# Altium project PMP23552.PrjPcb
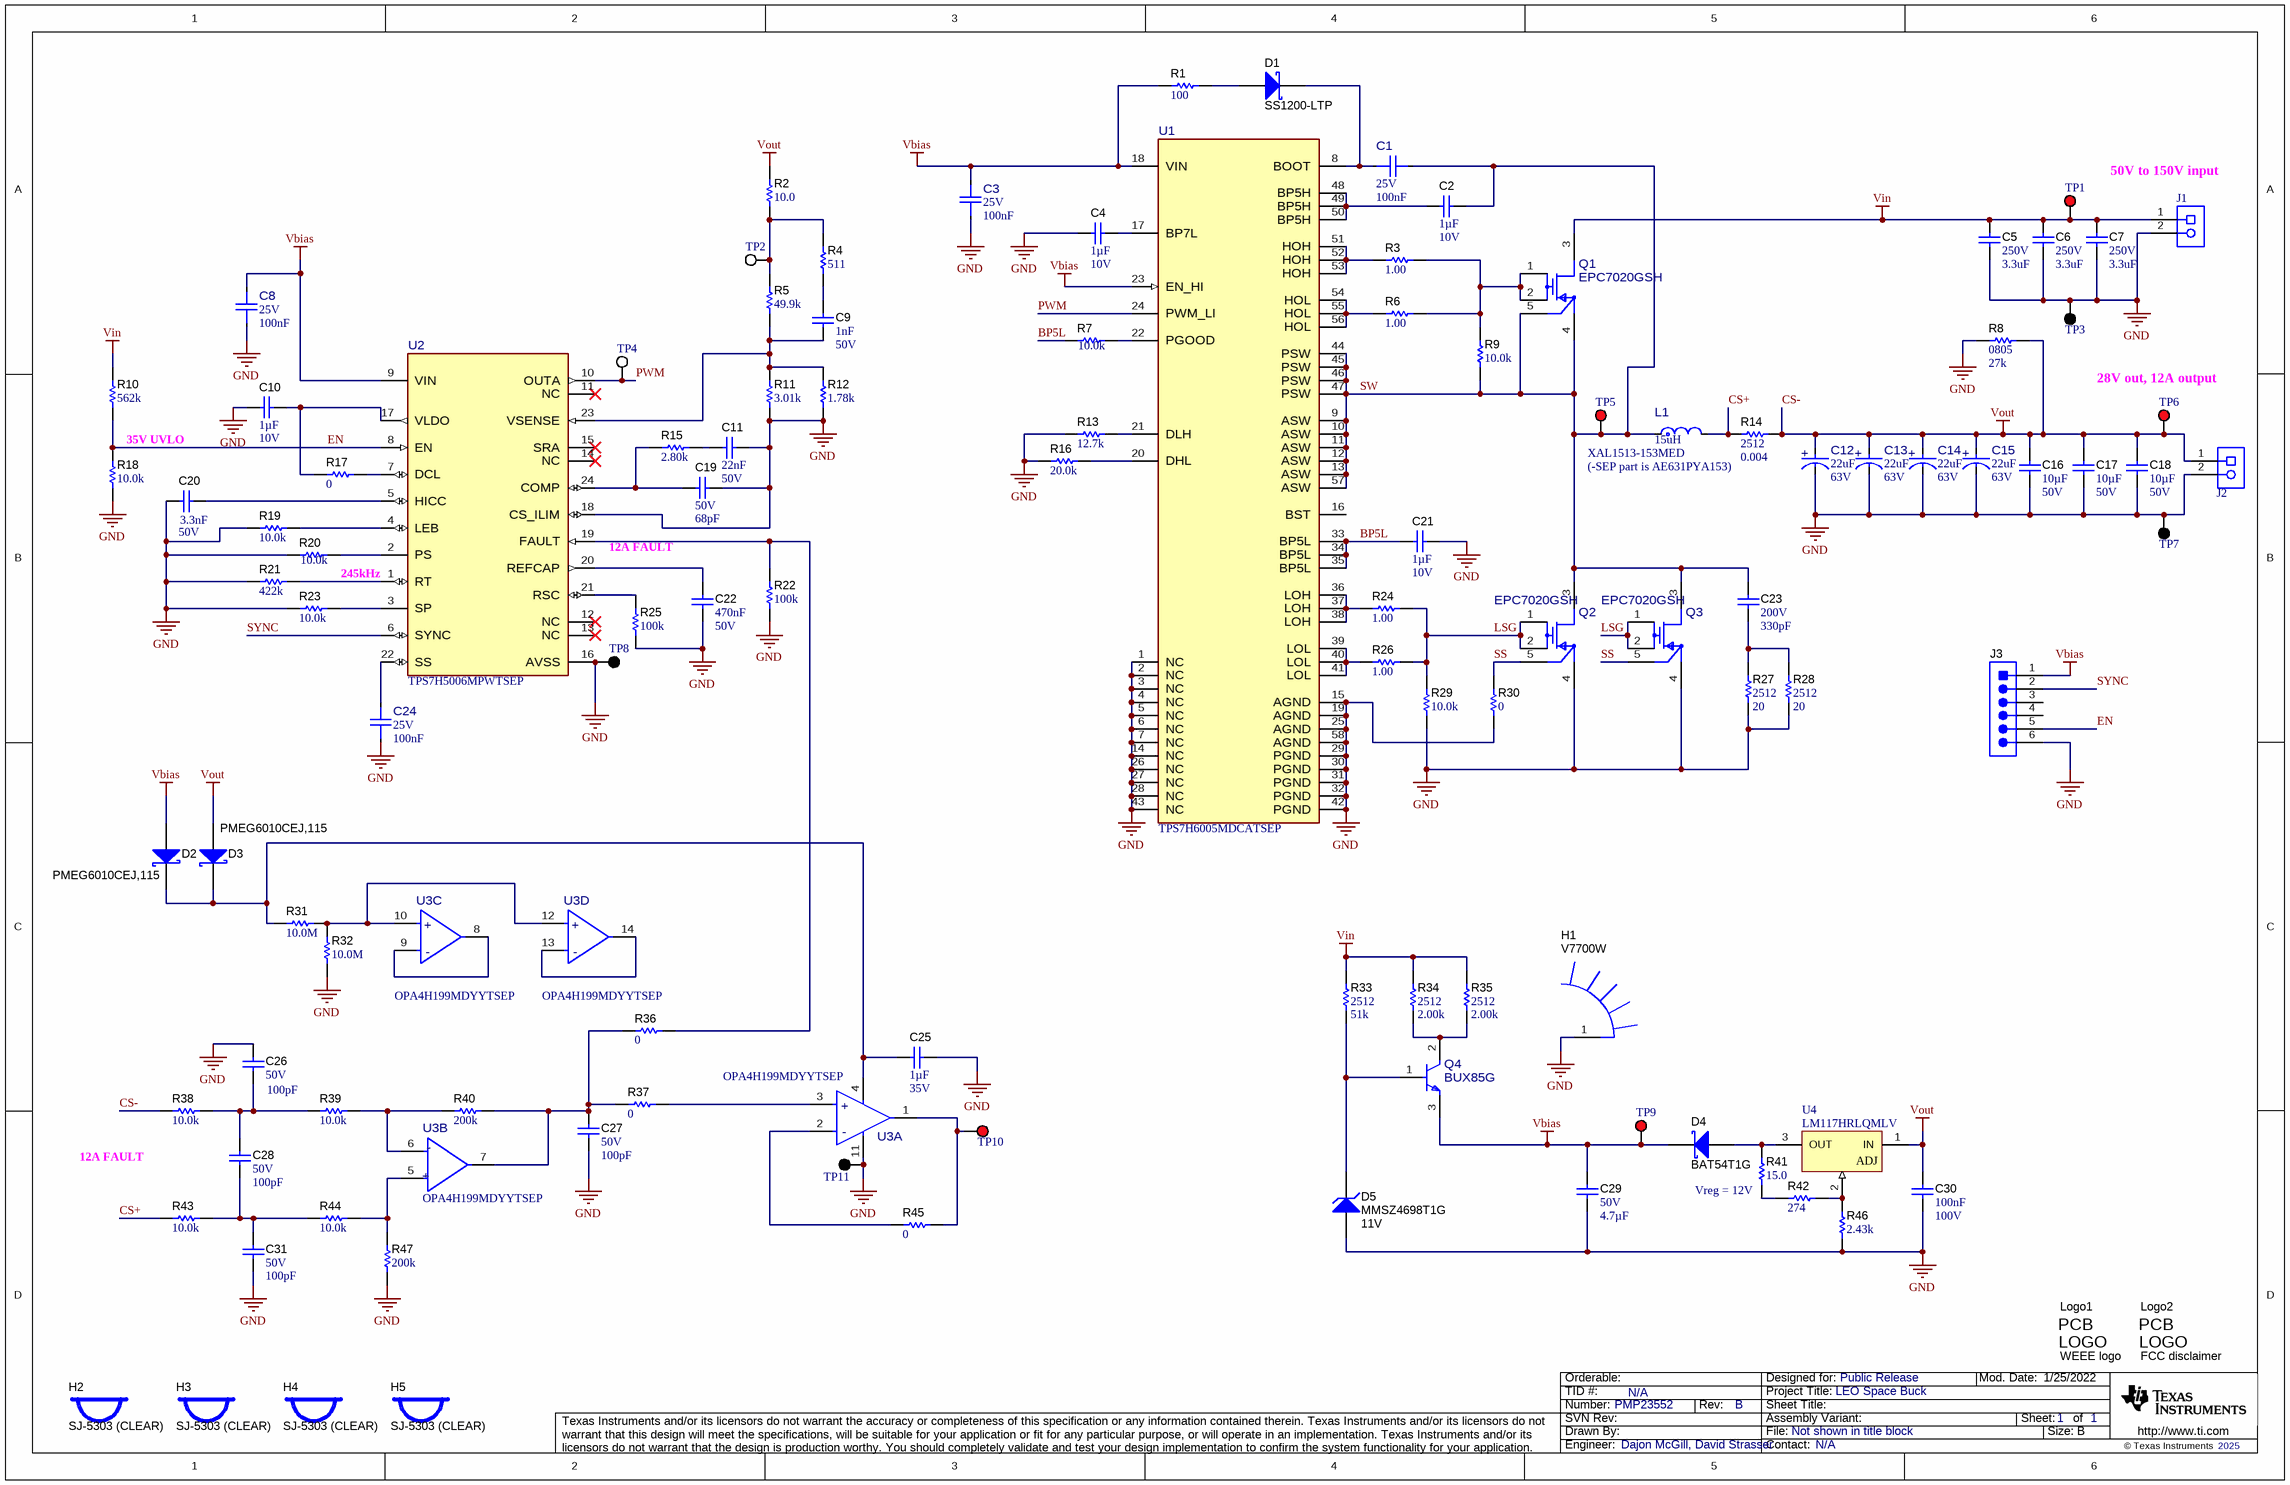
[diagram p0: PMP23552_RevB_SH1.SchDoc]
CopyrightYear: 2025; PCB_Layout: Dajon McGill; PCB_Rev: B; PRJ_Customer: Public Release; PRJ_Engineer: Dajon McGill, David Strasser; PRJ_Number: PMP23552; PRJ_Title: LEO Space Buck; SCH_Rev: B; TechSupport: N/A; TID: N/A
1 sheet, 113 parts. Net scope: global (net labels, ports and power ports of the same name join across sheets).
Board file: PPMP23552_RevB.PcbDoc

## Sheet PMP23552_RevB_SH1.SchDoc
size 431 x 279 mm; Date: Not shown in title block; ApprovedBy: Not shown in title block; CheckedBy: Not shown in title block; Author: Not shown in title block; CompanyName: Not shown in title block; Engineer: Not shown in title block; Organization: Not shown in title block; Address1: Not shown in title block; Address2: Not shown in title block; Address3: Not shown in title block; Address4: Not shown in title block; DocumentNumber: 1; Revision: Use project parameter SCH_Rev; SheetNumber: 1; SheetTotal: 1; PageSetup: Record=PageOptions¦CenterHorizontal=True¦CenterVertical=True¦PrintScale=1.00¦XCorrection=1.00¦YCorrection=1.00¦PrintKind=0¦BorderSize=5000000¦LeftOffset=0¦BottomOffset=0¦Orientation=2¦PaperLength=1000¦PaperWidth=1000¦Scale=100¦PaperSource=15¦PrintQuality=600¦MediaType=1¦DitherType=10¦PaperKind=Letter¦PrintScaleMode=1

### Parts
C1  VDC_V: 25V  Cap_F: 100nF  [FP-GCJ188R71E104KA12D_0603-MFG]  (hidden comment: GCJ188R71E104KA12D)
C2  Cap_F: 1µF  VDC_V: 10V  [0603]  (hidden comment: 885012206026)
C3  VDC_V: 25V  Cap_F: 100nF  [FP-GCJ188R71E104KA12D_0603-MFG]  (hidden comment: GCJ188R71E104KA12D)
C4  Cap_F: 1µF  VDC_V: 10V  [0603]  (hidden comment: 885012206026)
C5  VDC_V: 250V  ValueDisplayed: 3.3uF  [CKG57N]  (hidden comment: CKG57NX7T2E335M500JH)
C6  VDC_V: 250V  ValueDisplayed: 3.3uF  [CKG57N]  (hidden comment: CKG57NX7T2E335M500JH)
C7  VDC_V: 250V  ValueDisplayed: 3.3uF  [CKG57N]  (hidden comment: CKG57NX7T2E335M500JH)
C8  VDC_V: 25V  Cap_F: 100nF  [FP-GCJ188R71E104KA12D_0603-MFG]  (hidden comment: GCJ188R71E104KA12D)
C9  Cap_F: 1nF  VDC_V: 50V  [0603]  (hidden comment: C0603X102K5RACTU)
C10  Cap_F: 1µF  VDC_V: 10V  [0603]  (hidden comment: 885012206026)
C11  Cap_F: 22nF  VDC_V: 50V  [0603]  (hidden comment: C0603C223K5RACTU)
C12  ValueDisplayed: 22uF  VDC_V: 63V  [FP-T521X226M063ATE075_2917-MFG]  (hidden comment: T521X226M063ATE075)
C13  ValueDisplayed: 22uF  VDC_V: 63V  [FP-T521X226M063ATE075_2917-MFG]  (hidden comment: T521X226M063ATE075)
C14  ValueDisplayed: 22uF  VDC_V: 63V  [FP-T521X226M063ATE075_2917-MFG]  (hidden comment: T521X226M063ATE075)
C15  ValueDisplayed: 22uF  VDC_V: 63V  [FP-T521X226M063ATE075_2917-MFG]  (hidden comment: T521X226M063ATE075)
C16  ValueDisplayed: 10µF  VDC_V: 50V  [1210]  (hidden comment: GXM32ER71H106KA10)
C17  ValueDisplayed: 10µF  VDC_V: 50V  [1210]  (hidden comment: GXM32ER71H106KA10)
C18  ValueDisplayed: 10µF  VDC_V: 50V  [1210]  (hidden comment: GXM32ER71H106KA10)
C19  VDC_V: 50V  ValueDisplayed: 68pF  [0603]  (hidden comment: GCM1885C1H680JA16D)
C20  Cap_F: 3.3nF  VDC_V: 50V  [0603]  (hidden comment: 885012206086)
C21  Cap_F: 1µF  VDC_V: 10V  [0603]  (hidden comment: 885012206026)
C22  Cap_F: 470nF  VDC_V: 50V  [0603]  (hidden comment: CGA3E3X7R1H474K080AE)
C23  VDC_V: 200V  ValueDisplayed: 330pF  [0805_HV]  (hidden comment: 08052A331JAT2A)
C24  VDC_V: 25V  Cap_F: 100nF  [FP-GCJ188R71E104KA12D_0603-MFG]  (hidden comment: GCJ188R71E104KA12D)
C25  Cap_F: 1µF  VDC_V: 35V  [0603]  (hidden comment: CGA3E1X7R1V105K080AE)
C26  VDC_V: 50V  ValueDisplayed: 100pF  [0603]  (hidden comment: C0603C101F5GACTU)
C27  VDC_V: 50V  ValueDisplayed: 100pF  [0603]  (hidden comment: C0603C101F5GACTU)
C28  VDC_V: 50V  ValueDisplayed: 100pF  [0603]  (hidden comment: C0603C101F5GACTU)
C29  VDC_V: 50V  ValueDisplayed: 4.7µF  [1210_280]  (hidden comment: C1210C475K5RACAUTO)
C30  Cap_F: 100nF  VDC_V: 100V  [0603]  (hidden comment: HMK107B7104KAHT)
C31  VDC_V: 50V  ValueDisplayed: 100pF  [0603]  (hidden comment: C0603C101F5GACTU)
D1  SS1200-LTP  [SMA]
D2  PMEG6010CEJ,115  [SOD-323F]
D3  PMEG6010CEJ,115  [SOD-323F]
D4  BAT54T1G  [SOD-123]
D5  MMSZ4698T1G  value 11V  [SOD-123]
H1  V7700W  [ASMN_V7700W]
H2  SJ-5303 (CLEAR)  [Bumpon_SJ5003Transparent]
H3  SJ-5303 (CLEAR)  [Bumpon_SJ5003Transparent]
H4  SJ-5303 (CLEAR)  [Bumpon_SJ5003Transparent]
H5  SJ-5303 (CLEAR)  [Bumpon_SJ5003Transparent]
J1  ED120/2DS  [On-Shore_ED120_2DS]  (value not drawn)
J2  ED120/2DS  [On-Shore_ED120_2DS]  (value not drawn)
J3  61300611121  [WURTH_61300611121]  (value not drawn)
L1  value 15uH  [FP-XAL1513-153MED_SMT_IND_15MM2_16MM2-MFG]  (hidden comment: XAL1513-153MED)
Logo1  WEEE logo  [WEEE_Minimum]  (no BOM)
Logo2  FCC disclaimer  [FCC_disclaimer]  (no BOM)
Q1  EPC7020GSH  [FP-EPC7020GSH_FSMD-G-MFG]
Q2  EPC7020GSH  [FP-EPC7020GSH_FSMD-G-MFG]
Q3  EPC7020GSH  [FP-EPC7020GSH_FSMD-G-MFG]
Q4  BUX85G  [FP-BUX85G_TO-220-3-MFG]
R1  ValueDisplayed: 100  [0603]  (hidden comment: RC0603FR-07100RL)
R2  ValueDisplayed: 10.0  [0603]  (hidden comment: RC0603FR-0710RL)
R3  ValueDisplayed: 1.00  [0603]  (hidden comment: RC0603FR-071RL)
R4  ValueDisplayed: 511  [0603]  (hidden comment: RC0603FR-07511RL)
R5  ValueDisplayed: 49.9k  [0603]  (hidden comment: RC0603FR-0749K9L)
R6  ValueDisplayed: 1.00  [0603]  (hidden comment: RC0603FR-071RL)
R7  ValueDisplayed: 10.0k  [0603]  (hidden comment: M55342K12B10E0T)
R8  PackageReference: 0805  ValueDisplayed: 27k  [0805_HV]  (hidden comment: CRCW080527K0JNEA)
R9  ValueDisplayed: 10.0k  [0603]  (hidden comment: M55342K12B10E0T)
R10  ValueDisplayed: 562k  [0603]  (hidden comment: RC0603FR-07562KL)
R11  ValueDisplayed: 3.01k  [0603]  (hidden comment: RC0603FR-073K01L)
R12  ValueDisplayed: 1.78k  [0603]  (hidden comment: RC0603FR-071K78L)
R13  ValueDisplayed: 12.7k  [0603]  (hidden comment: RC0603FR-0712K7L)
R14  ValueDisplayed: 0.004  [2512]  (hidden comment: ERJ-M1WSF4M0U)
R15  ValueDisplayed: 2.80k  [0603]  (hidden comment: RC0603FR-072K8L)
R16  ValueDisplayed: 20.0k  [0603]  (hidden comment: ERJ-3EKF2002V)
R17  ValueDisplayed: 0  [0603]  (hidden comment: RMCF0603ZT0R00)
R18  ValueDisplayed: 10.0k  [0603]  (hidden comment: M55342K12B10E0T)
R19  ValueDisplayed: 10.0k  [0603]  (hidden comment: M55342K12B10E0T)
R20  ValueDisplayed: 10.0k  [0603]  (hidden comment: M55342K12B10E0T)
R21  ValueDisplayed: 422k  [0603]  (hidden comment: RC0603FR-07422KL)
R22  ValueDisplayed: 100k  [0603]  (hidden comment: RC0603FR-07100KL)
R23  ValueDisplayed: 10.0k  [0603]  (hidden comment: M55342K12B10E0T)
R24  ValueDisplayed: 1.00  [0603]  (hidden comment: RC0603FR-071RL)
R25  ValueDisplayed: 100k  [0603]  (hidden comment: RC0603FR-07100KL)
R26  ValueDisplayed: 1.00  [0603]  (hidden comment: RC0603FR-071RL)
R27  ValueDisplayed: 20  [2512]  (hidden comment: CRCW251220R0JNEG)
R28  ValueDisplayed: 20  [2512]  (hidden comment: CRCW251220R0JNEG)
R29  ValueDisplayed: 10.0k  [0603]  (hidden comment: M55342K12B10E0T)
R30  ValueDisplayed: 0  [0603]  (hidden comment: RMCF0603ZT0R00)
R31  ValueDisplayed: 10.0M  [0603]  (hidden comment: RC0603FR-0710ML)
R32  ValueDisplayed: 10.0M  [0603]  (hidden comment: RC0603FR-0710ML)
R33  ValueDisplayed: 51k  [2512]  (hidden comment: CRCW251251K0JNEG)
R34  ValueDisplayed: 2.00k  [2512]  (hidden comment: CRCW25122K00FKEG)
R35  ValueDisplayed: 2.00k  [2512]  (hidden comment: CRCW25122K00FKEG)
R36  ValueDisplayed: 0  [0603]  (hidden comment: RMCF0603ZT0R00)
R37  ValueDisplayed: 0  [0603]  (hidden comment: RMCF0603ZT0R00)
R38  ValueDisplayed: 10.0k  [0603]  (hidden comment: RG1608P-103-B-T5)
R39  ValueDisplayed: 10.0k  [0603]  (hidden comment: RG1608P-103-B-T5)
R40  ValueDisplayed: 200k  [0603]  (hidden comment: RT0603BRD07200KL)
R41  ValueDisplayed: 15.0  [0603]  (hidden comment: RC0603FR-0715RL)
R42  ValueDisplayed: 274  [0603]  (hidden comment: RC0603FR-07274RL)
R43  ValueDisplayed: 10.0k  [0603]  (hidden comment: RG1608P-103-B-T5)
R44  ValueDisplayed: 10.0k  [0603]  (hidden comment: RG1608P-103-B-T5)
R45  ValueDisplayed: 0  [0603]  (hidden comment: RMCF0603ZT0R00)
R46  ValueDisplayed: 2.43k  [0603]  (hidden comment: RC0603FR-072K43L)
R47  ValueDisplayed: 200k  [0603]  (hidden comment: RT0603BRD07200KL)
TP1  5000  [Keystone5000]  (value not drawn)
TP2  5002  [Keystone5002]  (value not drawn)
TP3  5001  [Keystone5001]  (value not drawn)
TP4  5002  [Keystone5002]  (value not drawn)
TP5  5000  [Keystone5000]  (value not drawn)
TP6  5000  [Keystone5000]  (value not drawn)
TP7  5001  [Keystone5001]  (value not drawn)
TP8  5001  [Keystone5001]  (value not drawn)
TP9  5000  [Keystone5000]  (value not drawn)
TP10  5000  [Keystone5000]  (value not drawn)
TP11  5001  [Keystone5001]  (value not drawn)
U1  TPS7H6005MDCATSEP  [DCA0056M-MFG]
U2  TPS7H5006MPWTSEP  [PW0024A-MFG]
U3  OPA4H199MDYYTSEP  [DYY0014A-MFG]  (parts A,B,C,D of 4)
U4  LM117HRLQMLV  [NDT0003A]

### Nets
CS-: C12.2(ANODE) C13.2(ANODE) C14.2(ANODE) C15.2(ANODE) C16.1 C17.1 C18.1 C30.1 D3.2(A) J2.1 R2.2 R8.1 R14.2 R38.1 TP6.1 U4.1(IN)  [also labelled Vout]
GND: C3.1 C4.2 C5.2 C6.2 C7.2 C8.1 C10.2 C11.1 C12.1(CATHODE) C13.1(CATHODE) C14.1(CATHODE) C15.1(CATHODE) C16.2 C17.2 C18.2 C19.1 C20.2 C21.1 C22.2 C24.1 C25.1 C26.1 C27.2 C29.2 C30.2 C31.2 D5.2(A) H1.1 J1.2 J2.2 J3.6 Q2.4(S) Q3.4(S) R8.2 R11.1 R12.1 R13.1 R16.1 R18.1 R19.2 R20.2 R21.1 R22.1 R23.2 R25.1 R27.2 R28.2 R29.1 R30.2 R32.1 R46.1 R47.1 TP3.1 TP7.1 TP8.1 TP11.1 U1.1(NC) U1.2(NC) U1.3(NC) U1.4(NC) U1.5(NC) U1.6(NC) U1.7(NC) U1.14(NC) U1.15(AGND) U1.19(AGND) U1.25(AGND) U1.26(NC) U1.27(NC) U1.28(NC) U1.29(PGND) U1.30(PGND) U1.31(PGND) U1.32(PGND) U1.42(PGND) U1.43(NC) U1.58(AGND) U2.16(AVSS) U2.18(CS_ILIM) U3.11(V-)
Vbias: C3.2 C8.2 C29.1 D2.2(A) D4.1(K) J3.1 Q4.3(E) R1.1 TP9.1 U1.18(VIN) U1.23(EN_HI) U2.9(VIN)
Vin: C5.1 C6.1 C7.1 J1.1 Q1.3(D) R10.2 R33.1 R34.2 R35.2 TP1.1
BP5L: C21.2 R7.2 U1.33(BP5L) U1.34(BP5L) U1.35(BP5L)
CS+: L1.2 R14.1 R43.1
EN: J3.5 R10.1 R18.2 U2.8(EN)
LSG: Q2.1(G) Q2.2(G) Q3.1(G) Q3.2(G) R24.2 R26.2 R29.2
PWM: TP4.1 U1.24(PWM_LI) U2.10(OUTA)
SS: Q2.5(SS) Q3.5(SS) R30.1
SW: C1.2 C2.1 C23.2 L1.1 Q1.4(S) Q1.5(SS) Q2.3(D) Q3.3(D) R9.1 TP5.1 U1.9(ASW) U1.10(ASW) U1.11(ASW) U1.12(ASW) U1.13(ASW) U1.44(PSW) U1.45(PSW) U1.46(PSW) U1.47(PSW) U1.57(ASW)
SYNC: J3.2 U2.6(SYNC)
NetC1_1: C1.1 D1.1(K) U1.8(BOOT)
NetC2_2: C2.2 U1.48(BP5H) U1.49(BP5H) U1.50(BP5H)
NetC4_1: C4.1 U1.17(BP7L)
NetC9_1: C9.1 R4.1
NetC9_2: C9.2 R5.1 R11.2 R12.2 U2.23(VSENSE)
NetC10_1: C10.1 R17.2 U2.17(VLDO)
NetC11_2: C11.2 R15.2
NetC19_2: C19.2 R15.1 U2.24(COMP)
NetC20_1: C20.1 U2.5(HICC)
NetC22_1: C22.1 U2.20(REFCAP)
NetC23_1: C23.1 R27.1 R28.1
NetC24_2: C24.2 U2.22(SS)
NetC25_2: C25.2 D2.1(K) D3.1(K) R31.1 U3.4(V+)
NetC26_2: C26.2 C28.1 R38.2 R39.1
NetC27_1: C27.1 R36.2 R37.1 R40.2 U3.7(OUT2)
NetC28_2: C28.2 C31.1 R43.2 R44.1
NetD1_2: D1.2(A) R1.2
NetD4_2: D4.2(A) R41.2 U4.3(OUT)
NetD5_1: D5.1(K) Q4.1(B) R33.2
NetQ1_1: Q1.1(G) Q1.2(G) R3.2 R6.2 R9.2
NetQ4_2: Q4.2(C) R34.1 R35.1
NetR2_1: R2.1 R4.2 R5.2 TP2.1
NetR3_1: R3.1 U1.51(HOH) U1.52(HOH) U1.53(HOH)
NetR6_1: R6.1 U1.54(HOL) U1.55(HOL) U1.56(HOL)
NetR7_1: R7.1 U1.22(PGOOD)
NetR13_2: R13.2 U1.21(DLH)
NetR16_2: R16.2 U1.20(DHL)
NetR17_1: R17.1 U2.7(DCL)
NetR19_1: R19.1 U2.4(LEB)
NetR20_1: R20.1 U2.2(PS)
NetR21_2: R21.2 U2.1(RT)
NetR22_2: R22.2 R36.1 U2.19(FAULT)
NetR23_1: R23.1 U2.3(SP)
NetR24_1: R24.1 U1.36(LOH) U1.37(LOH) U1.38(LOH)
NetR25_2: R25.2 U2.21(RSC)
NetR26_1: R26.1 U1.39(LOL) U1.40(LOL) U1.41(LOL)
NetR31_2: R31.2 R32.2 U3.10(IN3+) U3.12(IN4+)
NetR37_2: R37.2 U3.3(IN1+)
NetR39_2: R39.2 R40.1 U3.6(IN2-)
NetR41_1: R41.1 R42.1
NetR42_2: R42.2 R46.2 U4.2(ADJ)
NetR44_2: R44.2 R47.2 U3.5(IN2+)
NetR45_1: R45.1 TP10.1 U3.1(OUT1)
NetR45_2: R45.2 U3.2(IN1-)
NetU3_8: U3.8(OUT3) U3.9(IN3-)
NetU3_13: U3.13(IN4-) U3.14(OUT4)

Not connected (* = marked no-connect by the designer): J3 3 4; U1 16(BST); U2 11(NC)* 12(NC)* 13(NC)* 14(NC)* 15(SRA)*

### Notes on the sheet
- 50V to 150V input
- (near TP6) 28V out, 12A output
- 35V UVLO
- (-SEP part is AE631PYA153)
- 12A FAULT
- 245kHz
- (near R41) Vreg = 12V

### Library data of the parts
C1 C3 C8 C24 = CMP-0095670-2: Cap Ceramic 0.1uF 25V X7R 10% Pad SMD 0603 Soft Termination +125°C Automotive T/R; Manufacturer: Murata; Value: 100nF; AEC Qualified: Yes; AEC Grade: Grade 1; SizeZ_mm: 0.9mm; TempCo: 15%
C2 C4 C10 C21 = CMP-0064932-4: CAP, CERM, 1 uF, 10 V,+/- 10%, X7R, 0603; Manufacturer: Wurth Elektronik; TaMin_C: -55°C; Polarized: N; SizeAreaWB_mm2: 4.68; Value1: Unknown; U/M: EA; Value: 1uF; TaMax_C: 125°C; SizeZ_mm: 1; SizeX_mm: 1.6; SizeY_mm: 0.8; SizeArea_mm2: 1.28; AEC Category: Q200
C5-C7 = CMP-0009427-2: CAP, CERM, 3.3 uF, 250 V, +/- 20%, X7T, AEC-Q200 Grade 1, 6x5x5mm; Manufacturer: TDK; TaMin_C: -55°C; Polarized: N; SizeAreaWB_mm2: 56; Value1: Unknown; U/M: EA; Value: 3.3uF; TaMax_C: 125°C; SizeZ_mm: 5.5; SizeX_mm: 6; SizeY_mm: 5; Cap_Case: 2220; SizeArea_mm2: 30; AEC Qualified: Y; Cap_F: 3.3µF; AEC Grade: 1; AEC Category: Q200
C9 = CMP-0006976-5: CAP, CERM, 1000 pF, 50 V, +/- 10%, X7R, 0603; Manufacturer: Kemet; TaMin_C: -55°C; Polarized: N; SizeAreaWB_mm2: 4.68; Value1: Unknown; U/M: EA; Value: 1000pF; TaMax_C: 125°C; SizeZ_mm: 1; SizeX_mm: 1.6; SizeY_mm: 0.8; SizeArea_mm2: 1.28; AEC Category: Q200
C11 = CMP-0006901-4: CAP, CERM, 0.022 uF, 50 V, +/- 10%, X7R, 0603; Manufacturer: Kemet; TaMin_C: -55°C; Polarized: N; Value1: Unknown; U/M: EA; TaMax_C: 125°C; SizeAreaWB_mm2: 4.68; SizeZ_mm: 1; SizeX_mm: 1.6; SizeY_mm: 0.8; SizeArea_mm2: 1.28; AEC Category: Q200
C12-C15 = CMP-0124532-1: Cap Tant Polymer 22uF 63VDC X CASE 20% (7.3 X 4.3 X 4mm) SMD 7343-43 0.075 Ohm 125C T/R; Manufacturer: KEMET; AEC Qualified: No; Cap_F: 22µF; IRMS_A: 2.31A; SizeZ_mm: 4.3mm; Dissipation Factor: 10%; Esr: 75m; Leakage Current: 138.6uA; Life: 2000Hours; Standoff Height: 0mm; Value: 22µF
C16-C18 = CMP-0861001-1: CAP, CERM, 10 µF, 50 V,+/- 10%, X7R, 1210; Manufacturer: MuRata; SizeY_mm: 2.5; SizeAreaWB_mm2: 14.7; Value: 10uF; SizeZ_mm: 1.35; SizeArea_mm2: 8; Polarized: N; AEC Category: Q200; U/M: EA; TaMax_C: 125°C; TaMin_C: -55°C; SizeX_mm: 3.2
C19 = CMP-0007129-4: CAP, CERM, 68 pF, 50 V, +/- 5%, C0G/NP0, AEC-Q200 Grade 1, 0603; Manufacturer: MuRata; TaMin_C: -55°C; Polarized: N; SizeAreaWB_mm2: 4.68; Value1: Unknown; U/M: EA; Value: 68pF; TaMax_C: 125°C; SizeZ_mm: 1; SizeX_mm: 1.6; SizeY_mm: 0.8; SizeArea_mm2: 1.28; AEC Qualified: Y; AEC Category: Q200
C20 = CMP-0077942-1: CAP, CERM, 3300 pF, 50 V,+/- 10%, X7R, 0603; Manufacturer: Wurth Elektronik; TaMin_C: -55°C; Polarized: N; SizeAreaWB_mm2: 4.68; U/M: EA; Value: 3300pF; TaMax_C: 125°C; SizeZ_mm: 1; SizeX_mm: 1.6; SizeY_mm: 0.8; SizeArea_mm2: 1.28; AEC Category: Q200
C22 = CMP-0007097-4: CAP, CERM, 0.47 uF, 50 V, +/- 10%, X7R, AEC-Q200 Grade 1, 0603; Manufacturer: TDK; TaMin_C: -55°C; Polarized: N; SizeAreaWB_mm2: 4.68; Value1: Unknown; U/M: EA; Value: 0.47uF; TaMax_C: 125°C; SizeZ_mm: 1; SizeX_mm: 1.6; SizeY_mm: 0.8; SizeArea_mm2: 1.28; AEC Qualified: Y; AEC Category: Q200
C23 = CMP-0080810-1: CAP, CERM, 330 pF, 200 V,+/- 5%, C0G/NP0, 0805; Manufacturer: AVX; SizeAreaWB_mm2: 6.75; SizeArea_mm2: 2.5; AEC Qualified: N; AEC Category: Q200; Value: 330pF; TaMax_C: 125°C; SizeZ_mm: 1.45; TaMin_C: -55°C; SizeY_mm: 1.25; U/M: EA; SizeX_mm: 2; Cap_Case: 0805
C25 = CMP-0081259-1: CAP, CERM, 1 µF, 35 V,+/- 10%, X7R, AEC-Q200 Grade 1, 0603; Manufacturer: TDK; SizeAreaWB_mm2: 4.68; SizeArea_mm2: 1.28; AEC Qualified: Y; AEC Category: Q200; Value: 1uF; TaMax_C: 125°C; SizeZ_mm: 1; Polarized: N; TaMin_C: -55°C; SizeY_mm: 0.8; U/M: EA; SizeX_mm: 1.6
C26-C28 C31 = CMP-0080091-1: CAP, CERM, 100 pF, 50 V,+/- 1%, C0G/NP0, 0603; Manufacturer: Kemet; SizeAreaWB_mm2: 4.68; SizeArea_mm2: 1.28; AEC Qualified: N; AEC Category: Q200; Value: 100pF; TaMax_C: 125°C; SizeZ_mm: 1; Green_REACh: Passed; TaMin_C: -55°C; SizeY_mm: 0.8; Green_Lifecycle: Active; U/M: EA; SizeX_mm: 1.6
C29 = CMP-0079604-1: CAP, CERM, 4.7 µF, 50 V,+/- 10%, X7R, AEC-Q200 Grade 1, 1210; Manufacturer: Kemet; TaMin_C: -55°C; Polarized: N; SizeAreaWB_mm2: 14.7; U/M: EA; Value: 4.7uF; TaMax_C: 125°C; SizeZ_mm: 2.8; SizeX_mm: 3.2; SizeY_mm: 2.5; Cap_Case: 1210; SizeArea_mm2: 8; AEC Qualified: Y; AEC Grade: 1; AEC Category: Q200
C30 = CMP-0081011-1: CAP, CERM, 0.1 µF, 100 V,+/- 10%, X7R, AEC-Q200 Grade 1, 0603; Manufacturer: Taiyo Yuden; SizeAreaWB_mm2: 4.68; SizeArea_mm2: 1.28; AEC Qualified: Y; AEC Category: Q200; Value: 0.1uF; TaMax_C: 125°C; SizeZ_mm: 1; Polarized: N; TaMin_C: -55°C; SizeY_mm: 0.8; U/M: EA; SizeX_mm: 1.6; ValueDisplayed: 0.1µF
D1 = CMP-0028981-2: Diode, Schottky, 200 V, 1 A, SMA; Manufacturer: Micro Commercial Components; TJmax_C: 150°C; SizeArea_mm2: 16.3228; Io_A: 1A; AEC Qualified: N; SizeX_mm: 5.59; SizeZ_mm: 2.87; Vf_V: 920mV; Value: 200V; AEC Category: Q101; Value2: 0.92V; SizeY_mm: 2.92; SizeAreaWB_mm2: 37.3428
D2 D3 = CMP-0077011-2: Diode, Schottky, 60 V, 1 A, SOD-323F; Manufacturer: Nexperia; SizeX_mm: 2.5; TJmax_C: 150°C; SizeZ_mm: 0.8; Vr_V: 60V; Green_Lifecycle: Not Set; Value2: 0.66V; SizeAreaWB_mm2: 7.875; Green_REACh: Incomplete; Io_A: 1A; Value: 60V; SizeY_mm: 1.25; SizeArea_mm2: 3.125; Vf_V: 660mV; AEC Category: Q101
D4 = CMP-0028457-2: Diode, Schottky, 30 V, 0.2 A, SOD-123; Manufacturer: ON Semiconductor; SizeArea_mm2: 6.545; Io_A: 200mA; SizeX_mm: 3.85; Value1: 0.2A; SizeY_mm: 1.7; AEC Category: Q101; Vf_V: 800mV; TJmax_C: 125°C; Green_Lifecycle: Not Set; RJC_CperW: 174; Value: 30V; Value2: 0.8V; SizeAreaWB_mm2: 13.095; Green_REACh: Incomplete; SizeZ_mm: 1.35
D5 = CMP-0005741-4: Diode, Zener, 11 V, 500 mW, SOD-123; Manufacturer: ON Semiconductor; SizeY_mm: 1.7; AEC Category: Q101; Power_W: 500mW; SizeAreaWB_mm2: 13.095; SizeZ_mm: 1.35; SizeArea_mm2: 6.545; Value1: 0.5W; SizeX_mm: 3.85; RJA_CperW: 340
H1 = CMP-0067644-1: Heatsink SOT-32, TO-220; Manufacturer: Assman WSW
H2-H5 = CMP-0003620-1: Bumpon, Hemisphere, 0.44 X 0.20, Clear; Manufacturer: 3M
J1 J2 = CMP-0074910-1: Terminal Block, 5.08 mm, 2x1, Brass, TH; Manufacturer: On-Shore Technology; Cert_VDE: Y; CNHeader: False; Current_A: 15A; Green_Lifecycle: Not Set; Shrouded: N; Gender: Female; Green_REACh: Incomplete; Voltage_V: 300V; Row_Count: 1; Pitch_mm: 5.08; CT: True
J3 = CMP-0054801-2: Header, 2.54 mm, 6x1, Gold, TH; Manufacturer: Wurth Elektronik; Cert_UL: Y; Gender: Male; Row_Count: 1; Shrouded: N; Pitch_mm: 2.54
L1 = CMP-0035008-1: Power Inductors - SMD 15uH Shld 20% 22A 7.5mOhms AECQ2; Manufacturer: Coilcraft; AEC Grade: Grade 1; AEC Qualified: Yes; DCR_ohm: 7.5m; Ind_H: 15µH; Isat: 25.5A; Material: Composite; SizeZ_mm: 13mm; Self Resonant Frequency: 8MHz; Shrouded: true; TaMax_C: +125°C; TaMin_C: -40°C; Test Frequency: 1MHz
Logo1 = CMP-0074769-4: Manufacturer: Texas Instruments; CompType: IC; AEC Category: Q200
Logo2 = CMP-0074847-1: FCC_disclaimer
Q1-Q3 = CMP-0120049-1: MOSFET N-Channel 200 V 80A (Tc) Surface Mount 5-SMD; Manufacturer: EPC Space; AEC Qualified: No; QgTyp_nC: 13.5nC @ 5V; Rdson45_ohm: 9.5m; SizeZ_mm: 2.235mm; VdsMax_V: 200V; Vgs_V: 6V; ChMode: False; Input Capacitace At Vds: 1313pF @ 100V; Number Of Channels: 1; Pulse Drain Current: 200A; Rthja Max: 48°C/W; Threshold Vgs Max: 2.5V; Threshold Vgs Min: 0.8V; TJmax_C: +150°C
Q4 = CMP-0094657-1: Bipolar (BJT) Transistor NPN 450 V 2 A 4MHz 50 W Through Hole TO-220; Manufacturer: On Semiconductor; Emitter Base Voltage: 5V; Vcesat1_V: 1V; Rthja Max: 62.5°C/W; NPN: 1; TJmax_C: +150°C; SizeZ_mm: 19.85mm; Ciiva Ids: 2558954; AEC Qualified: No; Vceo_V: 450V; Import Ts: 1521844919; Fall Time Tf: 0.3us; Hfe Min: 30; Standoff Height: 2.8mm; Hfe Ss Testic: 0.1A; Power_W: 50W; IcRated_A: 3A; Value: 450V
R1 = CMP-0022736-4: RES, 100, 1%, 0.1 W, 0603; Manufacturer: Yageo; Power_W: 100mW; TempCo: 100 ppm/C; Value_Code: 100R; Value: 100; EIA_Code: E96; SizeX_mm: 1.6; SizeY_mm: 0.8; SizeZ_mm: 1; Value2: 0.1W; SizeArea_mm2: 1.28; AEC Qualified: N; VDC_V: 75V; AEC Category: Q200; SizeAreaWB_mm2: 4.68
R2 = CMP-0022751-4: RES, 10.0, 1%, 0.1 W, 0603; Manufacturer: Yageo; Power_W: 100mW; TempCo: 100 ppm/C; Value_Code: 10R0; Value: 10.0; EIA_Code: E96; Res_ohm: 10; SizeX_mm: 1.6; SizeY_mm: 0.8; SizeZ_mm: 1; Value2: 0.1W; SizeArea_mm2: 1.28; AEC Qualified: N; VDC_V: 75V; AEC Category: Q200; SizeAreaWB_mm2: 4.68
R3 R6 R24 R26 = CMP-0022900-4: RES, 1.00, 1%, 0.1 W, 0603; Manufacturer: Yageo; Power_W: 100mW; TempCo: 200 ppm/C; Value_Code: 1R00; Value: 1.00; EIA_Code: E96; Res_ohm: 1; SizeX_mm: 1.6; SizeY_mm: 0.8; Value2: 0.1W; SizeArea_mm2: 1.28; AEC Qualified: N; VDC_V: 75V; AEC Category: Q200; SizeAreaWB_mm2: 4.68
R4 = CMP-0023165-5: RES, 511, 1%, 0.1 W, 0603; Manufacturer: Yageo; Power_W: 100mW; TempCo: 100 ppm/C; Value_Code: 511R; Value: 511; EIA_Code: E96; SizeX_mm: 1.6; SizeY_mm: 0.8; SizeZ_mm: 1; Value2: 0.1W; SizeArea_mm2: 1.28; AEC Qualified: N; VDC_V: 75V; AEC Category: Q200; SizeAreaWB_mm2: 4.68
R5 = CMP-0023142-5: RES, 49.9 k, 1%, 0.1 W, 0603; Manufacturer: Yageo; Power_W: 100mW; TempCo: 100 ppm/C; Value_Code: 49k9; Value: 49.9k; EIA_Code: E96; SizeX_mm: 1.6; SizeY_mm: 0.8; SizeZ_mm: 1; Value2: 0.1W; SizeArea_mm2: 1.28; AEC Qualified: N; VDC_V: 75V; AEC Category: Q200; SizeAreaWB_mm2: 4.68
R7 R9 R18-R20 R23 R29 = CMP-0080488-1: RES, 10.0 k, 1%, 0.1 W, 0603; Manufacturer: TT Electronics/IRC; Power_W: 100mW; TempCo: 100 ppm/C; SizeAreaWB_mm2: 4.68; Value_Code: 10k0; Value: 10.0k; EIA_Code: E96; Res_ohm: 10k; SizeX_mm: 1.6; SizeY_mm: 0.8; SizeZ_mm: 1; Value2: 0.1W; SizeArea_mm2: 1.28; AEC Qualified: N; AEC Category: Q200
R8 = CMP-0020508-3: RES, 27 k, 5%, 0.125 W, AEC-Q200 Grade 0, 0805; Manufacturer: Vishay-Dale; Power_W: 125mW; TempCo: 200 ppm/C; Value_Code: 27k0; Value: 27k; EIA_Code: E24; SizeX_mm: 2; SizeY_mm: 1.25; SizeZ_mm: 1.45; Value2: 0.125W; SizeArea_mm2: 2.5; AEC Qualified: Y; VDC_V: 150V; AEC Category: Q200; AEC Grade: 0
R10 = CMP-0023184-4: RES, 562 k, 1%, 0.1 W, 0603; Manufacturer: Yageo; Power_W: 100mW; TempCo: 100 ppm/C; Value: 562k; EIA_Code: E96; SizeX_mm: 1.6; SizeY_mm: 0.8; SizeZ_mm: 1; Value2: 0.1W; SizeArea_mm2: 1.28; AEC Qualified: N; VDC_V: 75V; AEC Category: Q200; SizeAreaWB_mm2: 4.68
R11 = CMP-0023076-5: RES, 3.01 k, 1%, 0.1 W, 0603; Manufacturer: Yageo; Power_W: 100mW; TempCo: 100 ppm/C; Value_Code: 3k01; Value: 3.01k; EIA_Code: E96; SizeX_mm: 1.6; SizeY_mm: 0.8; SizeZ_mm: 1; Value2: 0.1W; SizeArea_mm2: 1.28; AEC Qualified: N; VDC_V: 75V; AEC Category: Q200; SizeAreaWB_mm2: 4.68
R12 = CMP-0022889-5: RES, 1.78 k, 1%, 0.1 W, 0603; Manufacturer: Yageo; Power_W: 100mW; TempCo: 100 ppm/C; Value_Code: 1k78; Value: 1.78k; EIA_Code: E96; SizeX_mm: 1.6; SizeY_mm: 0.8; SizeZ_mm: 1; Value2: 0.1W; SizeArea_mm2: 1.28; AEC Qualified: N; VDC_V: 75V; AEC Category: Q200; SizeAreaWB_mm2: 4.68
R13 = CMP-0022778-5: RES, 12.7 k, 1%, 0.1 W, 0603; Manufacturer: Yageo; Power_W: 100mW; TempCo: 100 ppm/C; Value_Code: 12k7; Value: 12.7k; EIA_Code: E96; SizeX_mm: 1.6; SizeY_mm: 0.8; SizeZ_mm: 1; Value2: 0.1W; SizeArea_mm2: 1.28; AEC Qualified: N; VDC_V: 75V; AEC Category: Q200; SizeAreaWB_mm2: 4.68
R14 = CMP-0015813-2: RES, 0.004, 1%, 1 W, 2512; Manufacturer: Panasonic; Power_W: 1W; TempCo: 350 ppm/C; Value_Code: 4L000; U/M: EA; Value: 0.004; Res_ohm: 4m; SizeX_mm: 6.3; SizeY_mm: 3.2; SizeZ_mm: 0.71; SizeArea_mm2: 20.16; AEC Category: Q200
R15 = CMP-0022998-5: RES, 2.80 k, 1%, 0.1 W, 0603; Manufacturer: Yageo; Power_W: 100mW; TempCo: 100 ppm/C; Value_Code: 2k80; Value: 2.80k; EIA_Code: E96; Res_ohm: 2.8k; SizeX_mm: 1.6; SizeY_mm: 0.8; SizeZ_mm: 1; Value2: 0.1W; SizeArea_mm2: 1.28; AEC Qualified: N; VDC_V: 75V; AEC Category: Q200; SizeAreaWB_mm2: 4.68
R16 = CMP-0022691-3: RES, 20.0 k, 1%, 0.1 W, AEC-Q200 Grade 0, 0603; Manufacturer: Panasonic; Power_W: 100mW; TempCo: 100 ppm/C; Value_Code: 20k0; U/M: EA; Value: 20.0k; Res_ohm: 20k; SizeX_mm: 1.6; SizeY_mm: 0.8; SizeZ_mm: 1; Value2: 0.1W; SizeArea_mm2: 1.28; AEC Qualified: Y; VDC_V: 75V; AEC Grade: 0; AEC Category: Q200; EIA_Code: E96
R17 R30 = CMP-0023343-3: RES, 0, 1%, 0.1 W, AEC-Q200 Grade 0, 0603; Manufacturer: Stackpole Electronics Inc; Power_W: 100mW; TempCo: ppm/C; U/M: EA; Value: 0; SizeX_mm: 1.6; SizeY_mm: 0.8; SizeZ_mm: 1; Value2: 0.1W; SizeArea_mm2: 1.28; AEC Qualified: Y; AEC Category: Q200
R21 = CMP-0023104-4: RES, 422 k, 1%, 0.1 W, 0603; Manufacturer: Yageo; Power_W: 100mW; TempCo: 100 ppm/C; Value: 422k; EIA_Code: E96; SizeX_mm: 1.6; SizeY_mm: 0.8; SizeZ_mm: 1; Value2: 0.1W; SizeArea_mm2: 1.28; AEC Qualified: N; VDC_V: 75V; AEC Category: Q200; SizeAreaWB_mm2: 4.68
R22 R25 = CMP-0022735-5: RES, 100 k, 1%, 0.1 W, 0603; Manufacturer: Yageo; Power_W: 100mW; TempCo: 100 ppm/C; Value: 100k; EIA_Code: E96; SizeX_mm: 1.6; SizeY_mm: 0.8; SizeZ_mm: 1; Value2: 0.1W; SizeArea_mm2: 1.28; AEC Qualified: N; VDC_V: 75V; AEC Category: Q200; SizeAreaWB_mm2: 4.68
R27 R28 = CMP-0015914-3: RES, 20, 5%, 1 W, AEC-Q200 Grade 0, 2512; Manufacturer: Vishay-Dale; Power_W: 1W; TempCo: 200 ppm/C; Value_Code: 20R0; Value: 20; EIA_Code: E24; SizeX_mm: 6.3; SizeY_mm: 3.2; SizeZ_mm: 0.71; SizeArea_mm2: 20.16; AEC Qualified: Y; VDC_V: 500V; AEC Grade: 0; AEC Category: Q200
R31 R32 = CMP-0022747-4: RES, 10.0 M, 1%, 0.1 W, 0603; Manufacturer: Yageo; Power_W: 100mW; TempCo: 100 ppm/C; Value_Code: 10M0; Value: 10.0Meg; EIA_Code: E96; Res_ohm: 10M; SizeX_mm: 1.6; SizeY_mm: 0.8; SizeZ_mm: 1; Value2: 0.1W; SizeArea_mm2: 1.28; AEC Qualified: N; VDC_V: 75V; AEC Category: Q200; SizeAreaWB_mm2: 4.68
R33 = CMP-0015977-3: RES, 51 k, 5%, 1 W, AEC-Q200 Grade 0, 2512; Manufacturer: Vishay-Dale; Power_W: 1W; TempCo: 200 ppm/C; Value_Code: 51k0; Value: 51k; EIA_Code: E24; SizeX_mm: 6.3; SizeY_mm: 3.2; SizeZ_mm: 0.71; SizeArea_mm2: 20.16; AEC Qualified: Y; VDC_V: 500V; AEC Grade: 0; AEC Category: Q200
R34 R35 = CMP-0015569-3: RES, 2.00 k, 1%, 1 W, AEC-Q200 Grade 0, 2512; Manufacturer: Vishay-Dale; Power_W: 1W; TempCo: 100 ppm/C; Value_Code: 2k00; Value: 2.00k; EIA_Code: E96; Res_ohm: 2k; SizeX_mm: 6.3; SizeY_mm: 3.2; SizeZ_mm: 0.71; SizeArea_mm2: 20.16; AEC Qualified: Y; VDC_V: 500V; AEC Grade: 0; AEC Category: Q200
R36 R37 R45 = CMP-0023343-2: RES, 0, 1%, 0.1 W, AEC-Q200 Grade 0, 0603; Manufacturer: Stackpole Electronics Inc; Power_W: 100mW; TempCo: ppm/C; U/M: EA; Value: 0; SizeX_mm: 1.6; SizeY_mm: 0.8; SizeZ_mm: 1; Value2: 0.1W; SizeArea_mm2: 1.28; AEC Qualified: Y; AEC Category: Q200
R38 R39 R43 R44 = CMP-0023404-3: RES, 10.0 k, 0.1%, 0.1 W, 0603; Manufacturer: Susumu Co Ltd; Power_W: 100mW; TempCo: 25 ppm/C; Value_Code: 10k0; U/M: EA; Value: 10.0k; EIA_Code: E192; Res_ohm: 10k; SizeX_mm: 1.6; SizeY_mm: 0.8; SizeZ_mm: 1; Value2: 0.1W; SizeArea_mm2: 1.28; VDC_V: 75V; AEC Category: Q200
R40 R47 = CMP-0023920-3: RES, 200 k, 0.1%, 0.1 W, 0603; Manufacturer: Yageo America; Power_W: 100mW; TempCo: 25 ppm/C; U/M: EA; Value: 200k; EIA_Code: E192; SizeX_mm: 1.6; SizeY_mm: 0.8; SizeZ_mm: 1; Value2: 0.1W; SizeArea_mm2: 1.28; VDC_V: 75V; AEC Category: Q200
R41 = CMP-0022819-4: RES, 15.0, 1%, 0.1 W, 0603; Manufacturer: Yageo; Power_W: 100mW; TempCo: 100 ppm/C; Value_Code: 15R0; Value: 15.0; EIA_Code: E96; Res_ohm: 15; SizeX_mm: 1.6; SizeY_mm: 0.8; SizeZ_mm: 1; Value2: 0.1W; SizeArea_mm2: 1.28; AEC Qualified: N; VDC_V: 75V; AEC Category: Q200; SizeAreaWB_mm2: 4.68
R42 = CMP-0022964-5: RES, 274, 1%, 0.1 W, 0603; Manufacturer: Yageo; Power_W: 100mW; TempCo: 100 ppm/C; Value_Code: 274R; Value: 274; EIA_Code: E96; SizeX_mm: 1.6; SizeY_mm: 0.8; SizeZ_mm: 1; Value2: 0.1W; SizeArea_mm2: 1.28; AEC Qualified: N; VDC_V: 75V; AEC Category: Q200; SizeAreaWB_mm2: 4.68
R46 = CMP-0022989-5: RES, 2.43 k, 1%, 0.1 W, 0603; Manufacturer: Yageo; Power_W: 100mW; TempCo: 100 ppm/C; Value_Code: 2k43; Value: 2.43k; EIA_Code: E96; SizeX_mm: 1.6; SizeY_mm: 0.8; SizeZ_mm: 1; Value2: 0.1W; SizeArea_mm2: 1.28; AEC Qualified: N; VDC_V: 75V; AEC Category: Q200; SizeAreaWB_mm2: 4.68
TP1 TP5 TP6 TP9 TP10 = CMP-0055137-2: Test Point, Miniature, Red, TH; Manufacturer: Keystone Electronics; Green_REACh: Passed; Green_Lifecycle: Active; ContactFinish: Silver; CNHeader: FALSE; CT: TRUE
TP2 TP4 = CMP-0055139-2: Test Point, Miniature, White, TH; Manufacturer: Keystone Electronics; ContactFinish: Silver; Green_REACh: Passed; CT: TRUE; Green_Lifecycle: Active; CNHeader: FALSE
TP3 TP7 TP8 TP11 = CMP-0055138-2: Test Point, Miniature, Black, TH; Manufacturer: Keystone Electronics; ContactFinish: Silver; CNHeader: FALSE; Green_Lifecycle: Active; Green_REACh: Passed; CT: TRUE
U1 = CMP-0120202-4: Manufacturer: Texas Instruments; SizeZ_mm: 1.2mm; Standoff Height: 0.05mm; AEC Category: Q200; CompType: IC
U2 = CMP-0094375-1: Radiation-Hardened 2 MHz Current Mode PWM Controllers in Space Enhanced Plastic; Manufacturer: Texas Instruments; Part Number: TPS7H5006MPWSEP; Min Supply Voltage: 4V; Standoff Height: 0.05mm; Output Type: AdjustableProgrammable; Max Supply Voltage: 14V; SizeZ_mm: 1.2mm; TJmax_C: +125°C; Switching Frequency: 100-2000MHz; Switching Topology: Buck,Flyback,Push-Pull,Other; AEC Qualified: No; Nominal Supply Current: 6.25-14mA; Max Duty Cycle: 100%; Number Of Outputs: 1
U3 = CMP-0037180-1: Space-enhanced-product, quad, 40-V 4.5-MHz rail-to-rail input and output operational amplifier 14-SOT-23-THIN -55 to +125; Manufacturer: Texas Instruments; SizeZ_mm: 1.1mm; AEC Qualified: No; Gain Bandwidth: 4.5MHz; Input Bias Current: 0.00001uA; Input Offset Voltage: 0.125mV; Max Dual Supply Voltage: 20V; Max Supply Voltage: 40V; Min Dual Supply Voltage: 1.35V; Min Supply Voltage: 2.7V; Nominal Supply Current: 560uA; Number Of Channels: 4; Output Current Per Channel: 75mA; Response Time: 2.5us; Standoff Height: 0mm; TaMax_C: +125°C; TaMin_C: -55°C; TJmax_C: +150°C; Voltage Gain: 145dB
U4 = CMP-0069993-1: 3-Terminal Adjustable Regulator, 3-pin TO-39; Manufacturer: Texas Instruments; High-Reliability: Y; CompType: LDO IC; PackageTopMarking: NSZSSXXYYA 5962R99517*05VXA LM117HRLQV Q; PowerWise: N

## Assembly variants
001: not fitted C30 R16 R45 R46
